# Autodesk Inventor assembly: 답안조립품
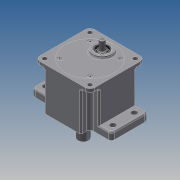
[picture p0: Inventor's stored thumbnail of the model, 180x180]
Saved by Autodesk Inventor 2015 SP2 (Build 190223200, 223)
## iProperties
Created: 2015-06
Part Number: 답안조립품
Document SubType Name: Assembly
Designer: AMC
Author: AMC
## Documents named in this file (12)
- C:\Users\AMC\Desktop\450620V1015\답안조립품.iam
- C:\Users\AMC\Desktop\450620V1015\M4x0.5x16.ipt
- C:\Users\AMC\Desktop\450620V1015\메인축.ipt
- C:\Users\AMC\Desktop\450620V1015\베어링 608.ipt
- 베어링 608.ipt
- C:\Users\AMC\Desktop\450620V1015\베어링 6003.ipt
- 베어링 6003.ipt
- C:\Users\AMC\Desktop\450620V1015\본체.ipt
- C:\Users\AMC\Desktop\450620V1015\서브축.ipt
- C:\Users\AMC\Desktop\450620V1015\오일실 8x22x7.ipt
- C:\Users\AMC\Desktop\450620V1015\오일실 17x32x8.ipt
- C:\Users\AMC\Desktop\450620V1015\커버.ipt
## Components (4 placed, 1 different names)
1. M4x0.5x12:1
2. M4x0.5x12:2
3. M4x0.5x12:3
4. M4x0.5x12:4
